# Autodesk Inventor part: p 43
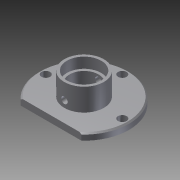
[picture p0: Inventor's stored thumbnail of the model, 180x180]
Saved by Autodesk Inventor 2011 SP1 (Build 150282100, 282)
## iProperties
Created: 2014-02
Part Number: p 43
Document SubType Name: Modeling
Designer: Administrator
Density: 1 g/cm^3
Author: Administrator
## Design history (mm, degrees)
sketch "草图1"
  geometry: C1 r 15 at (0, 0); 1 further point
  constraints: 1 centre point, 1 coincident
  dimensions: "d0" = 30 diameter of C1
extrude "拉伸1" new body sketch "草图1" distance "d1" = 17; taper "d2" = 0 deg
hole "Hole1" diameter "d5" = 26; stored, may be unused: countersink angle "d9" = 90 deg, drill point angle "d11" = 0 deg; dims "d3" = 10, "d4" = 10, "d6" = 6, "d7" = 4, "d8" = 2, "d10" = 8
hole "Hole2" diameter "d14" = 22; stored, may be unused: countersink angle "d18" = 90 deg, drill point angle "d20" = 118 deg; dims "d12" = 10, "d13" = 10, "d15" = 6, "d16" = 4, "d17" = 2, "d19" = 8
sketch "草图2"
  geometry: C1 r 11 at (0, 0) reference; C2 r 34 at (0, 0); 1 further point
  constraints: 1 centre point, 1 coincident
  dimensions: "d21" = 68 diameter of C2
extrude "拉伸2" cut sketch "草图2" distance "d22" = 5; taper "d23" = 0 deg
sketch "草图3"
  geometry: C1 r 34 at (0, 0); 1 further point
  constraints: 1 centre point, 1 coincident
  dimensions: "d24" = 68 diameter of C1
extrude "拉伸3" join sketch "草图3" distance "d25" = 5; taper "d26" = 0 deg
hole "Hole3" diameter "d29" = 22; stored, may be unused: countersink angle "d33" = 90 deg, drill point angle "d35" = 118 deg; dims "d27" = 10, "d28" = 10, "d30" = 6, "d31" = 4, "d32" = 2, "d34" = 8
sketch "草图4"
  geometry: C1 r 11 at (0, 0) reference; C2 r 34 at (0, 0) reference; C3 r 16.5 at (0, 0)
  constraints: 1 centre point, 1 coincident
  dimensions: "d36" = 33 diameter of C3
extrude "拉伸4" join sketch "草图4" distance "d37" = 8; taper "d38" = 0 deg
hole "Hole4" diameter "d41" = 26; stored, may be unused: countersink angle "d45" = 90 deg, drill point angle "d47" = 118 deg; dims "d39" = 10, "d40" = 10, "d42" = 6, "d43" = 4, "d44" = 2, "d46" = 8
sketch "草图5" dims "d48" = 58
  geometry: C1 r 15 at (0, 0) reference; C2 r 3.25 at (0, 29); 1 further point
  constraints: 1 centre point, 1 coincident, 1 vertical alignment, 2 other
  dimensions: "d49" = 6.5 diameter of C2
hole "Hole5" sketch "草图5" at (0, 29) diameter "d50" = 6.5; stored, may be unused: countersink angle "d54" = 90 deg, drill point angle "d56" = 118 deg; dims "d51" = 6, "d52" = 4, "d53" = 2, "d55" = 8
pattern_circular "环形阵列1" dims angle "d58" = 360 deg
chamfer "倒角1" distance "d60" = 1; stored, may be unused: second distance "d61" = 2, angle "d62" = 45 deg
sketch "草图6"
  geometry: L1 (-11, -3.798)-(11, -3.798) reference; L2 (-11, 9)-(11, 9) reference; C1 r 2.4 at (0, 5); 1 further point
  constraints: 1 centre point
  dimensions: "d64" = 4.8 diameter of C1
extrude "拉伸5" cut sketch "草图6" stored distance "d65" = 8; taper "d66" = 0 deg
node "工作平面1"
sketch "草图7"
  geometry: L1 (25.206, 1.641)-(25.206, -8.29); L2 (34, -1)-(-34, -1) reference; L3 (25.206, -8.29)-(-30.388, -8.29); L4 (-30.388, -8.29)-(-30.388, 3.791); L5 (-33, 0)-(33, 0) reference; L6 (-30.388, 3.791)-(25.206, 3.791); L7 (25.206, 3.791)-(25.206, 1.641); 1 further point
  constraints: 10 end point, 4 perpendicular, 1 parallel
extrude "拉伸6" cut sketch "草图7" distance "d68" = 17; taper "d69" = 0 deg
sketch "草图8"
  geometry: C1 r 16.5 at (0, 0) reference; C2 r 15.5 at (0, 0)
  constraints: 1 centre point, 1 coincident
  dimensions: "d70" = 31 diameter of C2
extrude "拉伸7" cut sketch "草图8" distance "d71" = 2; taper "d72" = 0 deg
node "实体1"
node "投影回路1"
other parameters: "d67" = -25
